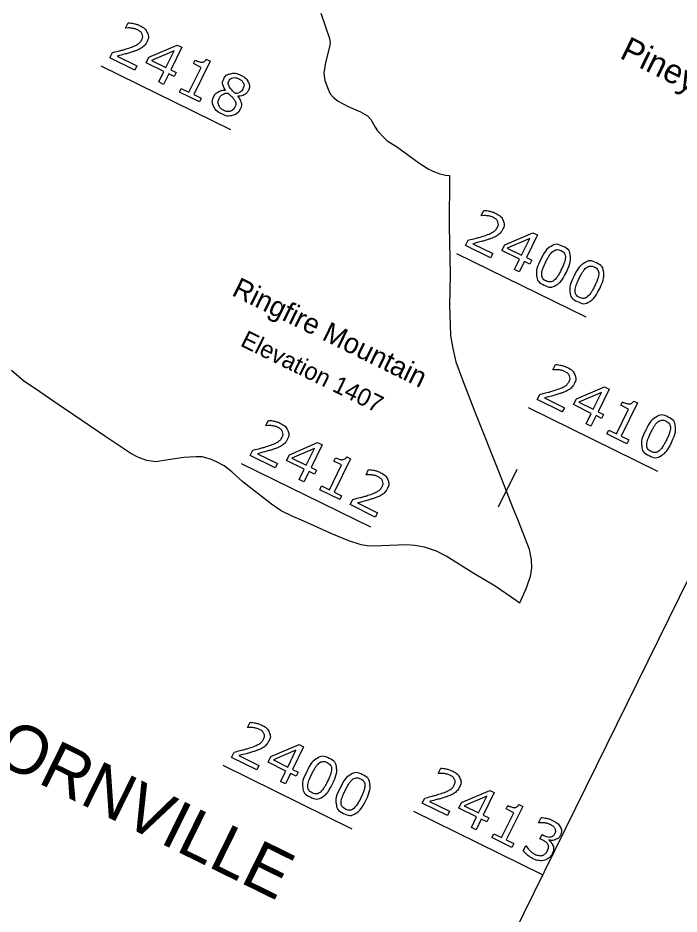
# Model space of a CAD drawing. Extents: x 1428128 to 1430390, y 857947 to 859822.
# Drawn here: x 1428559.3 to 1428679.5, y 859456.4 to 859619.3 of the extents above; entities that cross this region are included whole.
import ezdxf

# ---------------------------------------------------------------- set-up
doc = ezdxf.new("R2010")
doc.units = 0
doc.layers.add('Old_Level_1', color=7, linetype='Continuous')
doc.layers.add('Sheet Title CELL', color=7, linetype='Continuous')

msp = doc.modelspace()

# ---------------------------------------------------------------- linework, layer by layer
at = {"layer": 'Old_Level_1'}
for p, q in [((1428574.42, 859610.64), (1428597.94, 859599.07)), ((1428639.07, 859576.54), (1428662.53, 859564.99)), ((1428652.1, 859548.51), (1428675.56, 859536.97)), ((1428599.93, 859538.37), (1428623.4, 859526.82)), ((1428649.99, 859537.24), (1428646.62, 859530.4)), ((1428596.56, 859483.48), (1428620.03, 859471.94)), ((1428631.22, 859475.14), (1428654.6, 859463.64))]:
    msp.add_line(p, q, dxfattribs=at)
for points in [[(1428578.94, 859617.48), (1428578.9, 859617.51), (1428579.36, 859618.45)], [(1428587.73, 859608.67), (1428586.73, 859609.17), (1428585.8, 859607.27), (1428584.93, 859607.7), (1428585.87, 859609.59), (1428582.64, 859611.18), (1428583.15, 859612.22), (1428588.28, 859614.41), (1428589.11, 859614), (1428587.09, 859609.89), (1428588.09, 859609.4), (1428587.73, 859608.67)], [(1428586.22, 859610.32), (1428587.72, 859613.36), (1428583.61, 859611.6), (1428586.22, 859610.32)], [(1428580.58, 859609.84), (1428576.02, 859612.08), (1428576.49, 859613.03)], [(1428577.35, 859612.4), (1428580.97, 859610.62), (1428580.58, 859609.84)], [(1428592.33, 859604.06), (1428588.68, 859605.85), (1428589.02, 859606.54), (1428590.42, 859605.85), (1428592.64, 859610.36), (1428591.24, 859611.05), (1428591.54, 859611.67)], [(1428593.57, 859611.83), (1428594.27, 859611.49), (1428591.29, 859605.42), (1428592.66, 859604.75), (1428592.33, 859604.06)], [(1428597.05, 859606.2), (1428597.06, 859606.23)], [(1428599.28, 859605.09), (1428599.27, 859605.06)], [(1428643.6, 859583.37), (1428643.55, 859583.4), (1428644.02, 859584.35)], [(1428645.24, 859575.73), (1428640.68, 859577.97), (1428641.15, 859578.93)], [(1428652.39, 859574.57), (1428651.39, 859575.06), (1428650.45, 859573.16), (1428649.59, 859573.59), (1428650.52, 859575.49), (1428647.29, 859577.07), (1428647.81, 859578.11), (1428652.93, 859580.3), (1428653.77, 859579.89), (1428651.74, 859575.78), (1428652.74, 859575.29), (1428652.39, 859574.57)], [(1428650.88, 859576.21), (1428652.37, 859579.25), (1428648.27, 859577.5), (1428650.88, 859576.21)], [(1428642, 859578.29), (1428645.62, 859576.51), (1428645.24, 859575.73)], [(1428656.63, 859555.35), (1428656.58, 859555.38), (1428657.05, 859556.32)], [(1428665.42, 859546.54), (1428664.42, 859547.04), (1428663.49, 859545.14), (1428662.62, 859545.57), (1428663.55, 859547.46), (1428660.33, 859549.05), (1428660.84, 859550.09), (1428665.97, 859552.28), (1428666.8, 859551.87), (1428664.78, 859547.76), (1428665.78, 859547.27), (1428665.42, 859546.54)], [(1428663.91, 859548.19), (1428665.4, 859551.23), (1428661.3, 859549.47), (1428663.91, 859548.19)], [(1428658.27, 859547.71), (1428653.71, 859549.95), (1428654.18, 859550.9)], [(1428655.03, 859550.27), (1428658.65, 859548.49), (1428658.27, 859547.71)], [(1428671.26, 859549.7), (1428671.96, 859549.36), (1428668.98, 859543.29), (1428670.35, 859542.62), (1428670.01, 859541.93)], [(1428670.01, 859541.93), (1428666.37, 859543.72), (1428666.71, 859544.41), (1428668.11, 859543.72), (1428670.33, 859548.23), (1428668.93, 859548.92), (1428669.23, 859549.53)], [(1428604.45, 859545.21), (1428604.41, 859545.23), (1428604.87, 859546.18)], [(1428613.24, 859536.4), (1428612.24, 859536.89), (1428611.31, 859534.99), (1428610.44, 859535.42), (1428611.38, 859537.32), (1428608.15, 859538.9), (1428608.66, 859539.94), (1428613.79, 859542.13), (1428614.62, 859541.72), (1428612.6, 859537.62), (1428613.6, 859537.12), (1428613.24, 859536.4)], [(1428606.09, 859537.56), (1428601.53, 859539.81), (1428602, 859540.76)], [(1428602.85, 859540.12), (1428606.48, 859538.34), (1428606.09, 859537.56)], [(1428611.73, 859538.04), (1428613.23, 859541.08), (1428609.12, 859539.33), (1428611.73, 859538.04)], [(1428617.84, 859531.78), (1428614.19, 859533.58), (1428614.53, 859534.26), (1428615.93, 859533.57), (1428618.15, 859538.08), (1428616.75, 859538.77), (1428617.05, 859539.39)], [(1428619.08, 859539.56), (1428619.78, 859539.21), (1428616.8, 859533.15), (1428618.17, 859532.47), (1428617.84, 859531.78)], [(1428622.64, 859536.26), (1428622.6, 859536.28), (1428623.06, 859537.23)], [(1428624.28, 859528.61), (1428619.72, 859530.86), (1428620.19, 859531.81)], [(1428621.04, 859531.17), (1428624.67, 859529.39), (1428624.28, 859528.61)], [(1428601.09, 859490.32), (1428601.05, 859490.34), (1428601.51, 859491.29)], [(1428609.88, 859481.51), (1428608.88, 859482.01), (1428607.95, 859480.11), (1428607.08, 859480.54), (1428608.01, 859482.43), (1428604.79, 859484.02), (1428605.3, 859485.06), (1428610.43, 859487.25), (1428611.26, 859486.84), (1428609.24, 859482.73), (1428610.24, 859482.24), (1428609.88, 859481.51)], [(1428608.37, 859483.16), (1428609.87, 859486.2), (1428605.76, 859484.44), (1428608.37, 859483.16)], [(1428602.73, 859482.68), (1428598.17, 859484.92), (1428598.64, 859485.87)], [(1428599.49, 859485.24), (1428603.12, 859483.46), (1428602.73, 859482.68)], [(1428635.75, 859481.98), (1428635.71, 859482), (1428636.17, 859482.95)], [(1428644.54, 859473.17), (1428643.54, 859473.66), (1428642.61, 859471.77), (1428641.74, 859472.19), (1428642.67, 859474.09), (1428639.45, 859475.68), (1428639.96, 859476.72), (1428645.09, 859478.91), (1428645.92, 859478.5), (1428643.9, 859474.39), (1428644.9, 859473.9), (1428644.54, 859473.17)], [(1428637.39, 859474.33), (1428632.83, 859476.58), (1428633.3, 859477.53)], [(1428634.15, 859476.9), (1428637.78, 859475.11), (1428637.39, 859474.33)], [(1428643.03, 859474.82), (1428644.53, 859477.85), (1428640.42, 859476.1), (1428643.03, 859474.82)], [(1428650.38, 859476.33), (1428651.08, 859475.98), (1428648.1, 859469.92), (1428649.47, 859469.24), (1428649.13, 859468.56)], [(1428649.13, 859468.56), (1428645.49, 859470.35), (1428645.83, 859471.04), (1428647.23, 859470.35), (1428649.45, 859474.86), (1428648.05, 859475.55), (1428648.35, 859476.16)], [(1428654, 859473), (1428653.95, 859473.02), (1428654.41, 859473.97)], [(1428654.63, 859469.93), (1428654.22, 859470.13), (1428654.59, 859470.88), (1428654.9, 859470.72)], [(1428655.86, 859469.9), (1428655.82, 859469.84)], [(1428651.19, 859467.9), (1428651.65, 859468.84), (1428651.72, 859468.81)]]:
    msp.add_lwpolyline(points, dxfattribs=at)
for points in [[(1428579.36, 859618.45), (1428579.76, 859618.45), (1428580.36, 859618.32), (1428580.97, 859618.19), (1428581.47, 859617.94), (1428582.5, 859617.43), (1428582.85, 859616.64), (1428583.19, 859615.85), (1428582.77, 859615), (1428582.58, 859614.62), (1428582.32, 859614.33), (1428582.06, 859614.05), (1428581.72, 859613.84), (1428581.41, 859613.65), (1428581.04, 859613.5), (1428580.67, 859613.34), (1428580.17, 859613.18), (1428579.45, 859612.94), (1428578.71, 859612.75), (1428577.98, 859612.56), (1428577.35, 859612.4)], [(1428576.49, 859613.03), (1428577.17, 859613.21), (1428577.85, 859613.38), (1428578.52, 859613.55), (1428579.13, 859613.75), (1428580.42, 859614.16), (1428580.98, 859614.5), (1428581.55, 859614.83), (1428581.83, 859615.41), (1428582.09, 859615.93), (1428581.89, 859616.4), (1428581.69, 859616.86), (1428581.06, 859617.17), (1428580.65, 859617.37), (1428580.1, 859617.46), (1428579.55, 859617.56), (1428578.94, 859617.48)], [(1428591.54, 859611.67), (1428591.83, 859611.53), (1428592.18, 859611.41), (1428592.53, 859611.3), (1428592.74, 859611.31), (1428593, 859611.32), (1428593.21, 859611.43), (1428593.41, 859611.55), (1428593.57, 859611.83)], [(1428597.06, 859606.23), (1428596.66, 859606.78), (1428596.57, 859607.25), (1428596.48, 859607.73), (1428596.73, 859608.24), (1428597.11, 859609), (1428597.98, 859609.2), (1428598.85, 859609.4), (1428599.82, 859608.92), (1428600.83, 859608.43), (1428601.19, 859607.65), (1428601.55, 859606.87), (1428601.19, 859606.12), (1428600.96, 859605.67), (1428600.46, 859605.37), (1428599.96, 859605.07), (1428599.28, 859605.09)], [(1428600.29, 859606.55), (1428600.53, 859607.04), (1428600.3, 859607.51), (1428600.06, 859607.98), (1428599.48, 859608.26), (1428598.91, 859608.54), (1428598.42, 859608.45), (1428597.92, 859608.36), (1428597.69, 859607.9), (1428597.53, 859607.57), (1428597.6, 859607.25), (1428597.66, 859606.92), (1428597.94, 859606.55), (1428598.07, 859606.39), (1428598.32, 859606.1), (1428598.57, 859605.82), (1428598.83, 859605.58), (1428599.42, 859605.66), (1428599.75, 859605.9), (1428600.08, 859606.13), (1428600.29, 859606.55)], [(1428599.75, 859602.74), (1428599.32, 859601.87), (1428598.35, 859601.62), (1428597.39, 859601.38), (1428596.35, 859601.89), (1428595.26, 859602.43), (1428594.89, 859603.31), (1428594.52, 859604.19), (1428594.95, 859605.08), (1428595.23, 859605.64), (1428595.78, 859605.93), (1428596.33, 859606.22), (1428597.05, 859606.2)], [(1428598.78, 859603.11), (1428598.98, 859603.53), (1428598.92, 859603.87), (1428598.86, 859604.21), (1428598.45, 859604.72), (1428598.29, 859604.93), (1428598.08, 859605.14), (1428597.86, 859605.35), (1428597.52, 859605.71), (1428597, 859605.69), (1428596.57, 859605.43), (1428596.14, 859605.17), (1428595.9, 859604.69), (1428595.6, 859604.08), (1428595.83, 859603.48), (1428596.05, 859602.88), (1428596.7, 859602.56), (1428597.36, 859602.23), (1428597.92, 859602.38), (1428598.48, 859602.52), (1428598.78, 859603.11)], [(1428599.27, 859605.06), (1428599.77, 859604.48), (1428599.91, 859603.92), (1428600.05, 859603.35), (1428599.75, 859602.74)], [(1428644.02, 859584.35), (1428644.42, 859584.35), (1428645.02, 859584.21), (1428645.62, 859584.08), (1428646.12, 859583.83), (1428647.16, 859583.32), (1428647.5, 859582.53), (1428647.84, 859581.75), (1428647.42, 859580.89), (1428647.23, 859580.51), (1428646.97, 859580.22), (1428646.71, 859579.94), (1428646.38, 859579.73), (1428646.06, 859579.54), (1428645.69, 859579.39), (1428645.32, 859579.23), (1428644.82, 859579.07), (1428644.1, 859578.83), (1428643.37, 859578.64), (1428642.63, 859578.45), (1428642, 859578.29)], [(1428641.15, 859578.93), (1428641.82, 859579.1), (1428642.5, 859579.27), (1428643.18, 859579.44), (1428643.79, 859579.64), (1428645.07, 859580.05), (1428645.64, 859580.39), (1428646.2, 859580.73), (1428646.48, 859581.3), (1428646.74, 859581.82), (1428646.54, 859582.29), (1428646.34, 859582.76), (1428645.72, 859583.06), (1428645.31, 859583.26), (1428644.75, 859583.36), (1428644.2, 859583.45), (1428643.6, 859583.37)], [(1428659.01, 859573.14), (1428658.12, 859571.32), (1428657.13, 859570.75), (1428656.15, 859570.18), (1428654.96, 859570.77), (1428653.75, 859571.37), (1428653.61, 859572.5), (1428653.48, 859573.64), (1428654.35, 859575.42), (1428655.24, 859577.22), (1428656.22, 859577.8), (1428657.21, 859578.38), (1428658.41, 859577.79), (1428659.62, 859577.19), (1428659.75, 859576.04), (1428659.88, 859574.9), (1428659.01, 859573.14)], [(1428656.81, 859571.67), (1428657.15, 859571.96), (1428657.45, 859572.43), (1428657.75, 859572.89), (1428658.09, 859573.59), (1428658.43, 859574.28), (1428658.62, 859574.81), (1428658.82, 859575.35), (1428658.83, 859575.78), (1428658.84, 859576.21), (1428658.66, 859576.52), (1428658.47, 859576.83), (1428658.04, 859577.04), (1428657.62, 859577.25), (1428657.25, 859577.21), (1428656.89, 859577.17), (1428656.55, 859576.89), (1428656.23, 859576.63), (1428655.91, 859576.12), (1428655.59, 859575.61), (1428655.27, 859574.97), (1428654.92, 859574.26), (1428654.74, 859573.76), (1428654.55, 859573.26), (1428654.53, 859572.81), (1428654.51, 859572.38), (1428654.69, 859572.06), (1428654.87, 859571.74), (1428655.32, 859571.52), (1428655.75, 859571.31), (1428656.11, 859571.35), (1428656.48, 859571.39), (1428656.81, 859571.67)], [(1428665.07, 859570.16), (1428664.18, 859568.34), (1428663.2, 859567.77), (1428662.21, 859567.2), (1428661.02, 859567.79), (1428659.81, 859568.38), (1428659.67, 859569.52), (1428659.54, 859570.65), (1428660.42, 859572.44), (1428661.3, 859574.23), (1428662.29, 859574.81), (1428663.27, 859575.39), (1428664.47, 859574.8), (1428665.68, 859574.21), (1428665.81, 859573.06), (1428665.94, 859571.92), (1428665.07, 859570.16)], [(1428662.87, 859568.69), (1428663.21, 859568.97), (1428663.51, 859569.44), (1428663.81, 859569.91), (1428664.16, 859570.61), (1428664.49, 859571.29), (1428664.69, 859571.83), (1428664.88, 859572.36), (1428664.89, 859572.8), (1428664.9, 859573.22), (1428664.72, 859573.53), (1428664.53, 859573.84), (1428664.1, 859574.06), (1428663.68, 859574.26), (1428663.31, 859574.22), (1428662.95, 859574.19), (1428662.61, 859573.91), (1428662.29, 859573.65), (1428661.97, 859573.14), (1428661.65, 859572.63), (1428661.33, 859571.98), (1428660.99, 859571.28), (1428660.8, 859570.78), (1428660.62, 859570.28), (1428660.6, 859569.82), (1428660.57, 859569.4), (1428660.75, 859569.08), (1428660.93, 859568.76), (1428661.39, 859568.53), (1428661.81, 859568.33), (1428662.18, 859568.36), (1428662.54, 859568.4), (1428662.87, 859568.69)], [(1428657.05, 859556.32), (1428657.45, 859556.32), (1428658.05, 859556.19), (1428658.65, 859556.06), (1428659.15, 859555.81), (1428660.19, 859555.3), (1428660.53, 859554.51), (1428660.87, 859553.72), (1428660.45, 859552.87), (1428660.27, 859552.49), (1428660, 859552.2), (1428659.74, 859551.92), (1428659.41, 859551.71), (1428659.09, 859551.52), (1428658.72, 859551.37), (1428658.35, 859551.21), (1428657.85, 859551.05), (1428657.13, 859550.81), (1428656.4, 859550.62), (1428655.66, 859550.43), (1428655.03, 859550.27)], [(1428654.18, 859550.9), (1428654.85, 859551.08), (1428655.53, 859551.25), (1428656.21, 859551.42), (1428656.82, 859551.62), (1428658.1, 859552.03), (1428658.67, 859552.37), (1428659.23, 859552.7), (1428659.52, 859553.28), (1428659.77, 859553.8), (1428659.57, 859554.27), (1428659.37, 859554.73), (1428658.75, 859555.04), (1428658.34, 859555.24), (1428657.79, 859555.33), (1428657.23, 859555.43), (1428656.63, 859555.35)], [(1428669.23, 859549.53), (1428669.51, 859549.39), (1428669.86, 859549.28), (1428670.21, 859549.17), (1428670.42, 859549.18), (1428670.69, 859549.19), (1428670.89, 859549.3), (1428671.1, 859549.42), (1428671.26, 859549.7)], [(1428678.11, 859542.13), (1428677.21, 859540.32), (1428676.23, 859539.75), (1428675.24, 859539.18), (1428674.05, 859539.77), (1428672.84, 859540.36), (1428672.7, 859541.5), (1428672.57, 859542.63), (1428673.45, 859544.41), (1428674.33, 859546.21), (1428675.32, 859546.79), (1428676.31, 859547.37), (1428677.5, 859546.78), (1428678.71, 859546.18), (1428678.84, 859545.04), (1428678.97, 859543.89), (1428678.11, 859542.13)], [(1428602, 859540.76), (1428602.68, 859540.93), (1428603.36, 859541.1), (1428604.03, 859541.27), (1428604.64, 859541.47), (1428605.93, 859541.88), (1428606.49, 859542.22), (1428607.06, 859542.56), (1428607.34, 859543.13), (1428607.6, 859543.65), (1428607.4, 859544.12), (1428607.19, 859544.59), (1428606.57, 859544.89), (1428606.16, 859545.1), (1428605.61, 859545.19), (1428605.06, 859545.28), (1428604.45, 859545.21)], [(1428604.87, 859546.18), (1428605.27, 859546.18), (1428605.87, 859546.04), (1428606.47, 859545.91), (1428606.98, 859545.66), (1428608.01, 859545.15), (1428608.36, 859544.36), (1428608.7, 859543.58), (1428608.28, 859542.72), (1428608.09, 859542.34), (1428607.83, 859542.05), (1428607.57, 859541.77), (1428607.23, 859541.57), (1428606.92, 859541.37), (1428606.55, 859541.22), (1428606.18, 859541.06), (1428605.67, 859540.9), (1428604.96, 859540.67), (1428604.22, 859540.47), (1428603.49, 859540.28), (1428602.85, 859540.12)], [(1428675.91, 859540.66), (1428676.24, 859540.95), (1428676.54, 859541.42), (1428676.84, 859541.89), (1428677.19, 859542.58), (1428677.53, 859543.27), (1428677.72, 859543.81), (1428677.91, 859544.34), (1428677.92, 859544.77), (1428677.94, 859545.2), (1428677.75, 859545.51), (1428677.56, 859545.82), (1428677.13, 859546.03), (1428676.71, 859546.24), (1428676.35, 859546.2), (1428675.98, 859546.16), (1428675.64, 859545.89), (1428675.32, 859545.63), (1428675, 859545.12), (1428674.68, 859544.6), (1428674.37, 859543.96), (1428674.02, 859543.26), (1428673.83, 859542.76), (1428673.65, 859542.26), (1428673.63, 859541.8), (1428673.6, 859541.37), (1428673.78, 859541.05), (1428673.97, 859540.73), (1428674.42, 859540.51), (1428674.84, 859540.3), (1428675.21, 859540.34), (1428675.58, 859540.38), (1428675.91, 859540.66)], [(1428617.05, 859539.39), (1428617.34, 859539.25), (1428617.69, 859539.14), (1428618.03, 859539.02), (1428618.25, 859539.03), (1428618.51, 859539.04), (1428618.72, 859539.16), (1428618.92, 859539.27), (1428619.08, 859539.56)], [(1428623.06, 859537.23), (1428623.46, 859537.23), (1428624.06, 859537.09), (1428624.66, 859536.96), (1428625.17, 859536.71), (1428626.2, 859536.2), (1428626.54, 859535.42), (1428626.89, 859534.63), (1428626.47, 859533.77), (1428626.28, 859533.39), (1428626.02, 859533.11), (1428625.76, 859532.82), (1428625.42, 859532.62), (1428625.11, 859532.42), (1428624.74, 859532.27), (1428624.37, 859532.11), (1428623.86, 859531.95), (1428623.15, 859531.72), (1428622.41, 859531.52), (1428621.68, 859531.33), (1428621.04, 859531.17)], [(1428620.19, 859531.81), (1428620.87, 859531.98), (1428621.54, 859532.15), (1428622.22, 859532.32), (1428622.83, 859532.52), (1428624.12, 859532.93), (1428624.68, 859533.27), (1428625.25, 859533.61), (1428625.53, 859534.18), (1428625.79, 859534.7), (1428625.58, 859535.17), (1428625.38, 859535.64), (1428624.76, 859535.94), (1428624.35, 859536.15), (1428623.8, 859536.24), (1428623.25, 859536.33), (1428622.64, 859536.26)], [(1428601.51, 859491.29), (1428601.91, 859491.29), (1428602.51, 859491.16), (1428603.11, 859491.03), (1428603.61, 859490.78), (1428604.65, 859490.27), (1428604.99, 859489.48), (1428605.34, 859488.69), (1428604.92, 859487.84), (1428604.73, 859487.46), (1428604.47, 859487.17), (1428604.21, 859486.89), (1428603.87, 859486.68), (1428603.56, 859486.49), (1428603.19, 859486.34), (1428602.81, 859486.18), (1428602.31, 859486.02), (1428601.6, 859485.78), (1428600.86, 859485.59), (1428600.13, 859485.4), (1428599.49, 859485.24)], [(1428598.64, 859485.87), (1428599.32, 859486.05), (1428599.99, 859486.22), (1428600.67, 859486.39), (1428601.28, 859486.59), (1428602.57, 859487), (1428603.13, 859487.34), (1428603.7, 859487.67), (1428603.98, 859488.25), (1428604.24, 859488.77), (1428604.03, 859489.24), (1428603.83, 859489.7), (1428603.21, 859490.01), (1428602.8, 859490.21), (1428602.25, 859490.3), (1428601.7, 859490.4), (1428601.09, 859490.32)], [(1428616.5, 859480.09), (1428615.61, 859478.27), (1428614.63, 859477.7), (1428613.64, 859477.13), (1428612.45, 859477.72), (1428611.24, 859478.31), (1428611.1, 859479.45), (1428610.97, 859480.58), (1428611.85, 859482.37), (1428612.73, 859484.16), (1428613.72, 859484.74), (1428614.7, 859485.32), (1428615.9, 859484.73), (1428617.11, 859484.14), (1428617.24, 859482.99), (1428617.37, 859481.85), (1428616.5, 859480.09)], [(1428614.31, 859478.62), (1428614.64, 859478.91), (1428614.94, 859479.37), (1428615.24, 859479.84), (1428615.59, 859480.54), (1428615.93, 859481.23), (1428616.12, 859481.76), (1428616.31, 859482.29), (1428616.32, 859482.73), (1428616.34, 859483.15), (1428616.15, 859483.46), (1428615.96, 859483.78), (1428615.53, 859483.99), (1428615.11, 859484.2), (1428614.75, 859484.16), (1428614.38, 859484.12), (1428614.04, 859483.84), (1428613.72, 859483.58), (1428613.4, 859483.07), (1428613.08, 859482.56), (1428612.76, 859481.91), (1428612.42, 859481.21), (1428612.23, 859480.71), (1428612.05, 859480.21), (1428612.03, 859479.75), (1428612, 859479.33), (1428612.18, 859479.01), (1428612.37, 859478.69), (1428612.82, 859478.47), (1428613.24, 859478.26), (1428613.61, 859478.3), (1428613.98, 859478.33), (1428614.31, 859478.62)], [(1428636.17, 859482.95), (1428636.57, 859482.95), (1428637.17, 859482.82), (1428637.77, 859482.68), (1428638.28, 859482.44), (1428639.31, 859481.93), (1428639.65, 859481.14), (1428640, 859480.35), (1428639.58, 859479.5), (1428639.39, 859479.11), (1428639.13, 859478.83), (1428638.87, 859478.54), (1428638.53, 859478.34), (1428638.22, 859478.15), (1428637.85, 859477.99), (1428637.48, 859477.84), (1428636.97, 859477.68), (1428636.26, 859477.44), (1428635.52, 859477.25), (1428634.79, 859477.06), (1428634.15, 859476.9)], [(1428622.57, 859477.1), (1428621.67, 859475.29), (1428620.69, 859474.72), (1428619.71, 859474.15), (1428618.51, 859474.74), (1428617.3, 859475.33), (1428617.17, 859476.47), (1428617.03, 859477.6), (1428617.91, 859479.38), (1428618.79, 859481.18), (1428619.78, 859481.76), (1428620.77, 859482.34), (1428621.96, 859481.75), (1428623.18, 859481.15), (1428623.3, 859480.01), (1428623.43, 859478.86), (1428622.57, 859477.1)], [(1428620.37, 859475.63), (1428620.71, 859475.92), (1428621.01, 859476.39), (1428621.31, 859476.86), (1428621.65, 859477.55), (1428621.99, 859478.24), (1428622.18, 859478.78), (1428622.37, 859479.31), (1428622.39, 859479.74), (1428622.4, 859480.17), (1428622.21, 859480.48), (1428622.03, 859480.79), (1428621.6, 859481), (1428621.17, 859481.21), (1428620.81, 859481.17), (1428620.44, 859481.13), (1428620.1, 859480.86), (1428619.79, 859480.6), (1428619.47, 859480.09), (1428619.14, 859479.57), (1428618.83, 859478.93), (1428618.48, 859478.23), (1428618.3, 859477.73), (1428618.11, 859477.23), (1428618.09, 859476.77), (1428618.06, 859476.34), (1428618.25, 859476.02), (1428618.43, 859475.7), (1428618.88, 859475.48), (1428619.31, 859475.27), (1428619.67, 859475.31), (1428620.04, 859475.35), (1428620.37, 859475.63)], [(1428633.3, 859477.53), (1428633.98, 859477.7), (1428634.65, 859477.87), (1428635.33, 859478.05), (1428635.94, 859478.24), (1428637.23, 859478.66), (1428637.79, 859478.99), (1428638.36, 859479.33), (1428638.64, 859479.9), (1428638.9, 859480.43), (1428638.69, 859480.89), (1428638.49, 859481.36), (1428637.87, 859481.67), (1428637.46, 859481.87), (1428636.91, 859481.96), (1428636.36, 859482.05), (1428635.75, 859481.98)], [(1428648.35, 859476.16), (1428648.64, 859476.02), (1428648.99, 859475.91), (1428649.33, 859475.8), (1428649.55, 859475.8), (1428649.81, 859475.81), (1428650.01, 859475.93), (1428650.22, 859476.04), (1428650.38, 859476.33)], [(1428654.9, 859470.72), (1428655.59, 859470.38), (1428656.14, 859470.47), (1428656.69, 859470.55), (1428656.96, 859471.11), (1428657.08, 859471.35), (1428657.07, 859471.59), (1428657.06, 859471.82), (1428656.93, 859472.03), (1428656.79, 859472.24), (1428656.59, 859472.4), (1428656.39, 859472.55), (1428656.11, 859472.69), (1428655.68, 859472.9), (1428655.12, 859472.99), (1428654.56, 859473.07), (1428654, 859473)], [(1428654.41, 859473.97), (1428654.81, 859473.97), (1428655.41, 859473.84), (1428656.02, 859473.71), (1428656.52, 859473.46), (1428657.01, 859473.22), (1428657.34, 859472.94), (1428657.67, 859472.67), (1428657.88, 859472.32), (1428658.1, 859471.94), (1428658.11, 859471.55), (1428658.13, 859471.16), (1428657.93, 859470.75), (1428657.65, 859470.19), (1428657.05, 859469.97), (1428656.45, 859469.74), (1428655.86, 859469.9)], [(1428651.72, 859468.81), (1428651.98, 859468.36), (1428652.42, 859467.94), (1428652.86, 859467.52), (1428653.34, 859467.28), (1428653.63, 859467.14), (1428653.99, 859467.08), (1428654.36, 859467.01), (1428654.65, 859467.1), (1428654.96, 859467.2), (1428655.18, 859467.39), (1428655.4, 859467.58), (1428655.58, 859467.95), (1428655.76, 859468.31), (1428655.76, 859468.6), (1428655.76, 859468.9), (1428655.62, 859469.13), (1428655.49, 859469.37), (1428655.22, 859469.57), (1428654.96, 859469.76), (1428654.63, 859469.93)], [(1428655.82, 859469.84), (1428656.02, 859469.69), (1428656.25, 859469.44), (1428656.47, 859469.19), (1428656.58, 859468.92)], [(1428656.58, 859468.92), (1428656.7, 859468.62), (1428656.7, 859468.26), (1428656.69, 859467.89), (1428656.46, 859467.43), (1428656.24, 859466.96), (1428655.88, 859466.66), (1428655.52, 859466.36), (1428655.08, 859466.22), (1428654.59, 859466.07), (1428654.05, 859466.15), (1428653.52, 859466.22), (1428652.97, 859466.49), (1428652.41, 859466.77), (1428651.93, 859467.17), (1428651.46, 859467.57), (1428651.19, 859467.9)]]:
    msp.add_open_spline(points, degree=3, dxfattribs=at)
at = {"layer": 'Sheet Title CELL'}
msp.add_line((1428763.48, 859684.67), (1428622.2, 859397.54), dxfattribs=at)
for points in [[(1428614.37, 859620.23), (1428615.93, 859615.62), (1428616.07, 859614.77), (1428615.9, 859613.85), (1428615.23, 859611.21), (1428614.92, 859609.28), (1428615.14, 859607.95), (1428615.71, 859606.42), (1428616.09, 859605.55), (1428616.66, 859604.86), (1428617.55, 859604.2), (1428619.38, 859603.27), (1428621.6, 859602.27), (1428622.84, 859601.54), (1428623.46, 859600.89), (1428624.24, 859599.51), (1428624.68, 859598.82), (1428625.97, 859597.5), (1428626.47, 859597), (1428628.11, 859595.94), (1428630.38, 859594.33), (1428632.21, 859592.99), (1428633.9, 859591.91), (1428634.75, 859591.49), (1428635.99, 859591.01), (1428637.02, 859590.75), (1428637.77, 859590.67)], [(1428637.77, 859590.67), (1428637.73, 859581.49), (1428637.87, 859572.65), (1428637.77, 859567.12), (1428637.98, 859561.63), (1428638.35, 859559.27), (1428638.94, 859556.8), (1428640.11, 859553.57), (1428642.39, 859547.71), (1428646.8, 859536.67), (1428649.21, 859530.38), (1428650.25, 859527.9), (1428652.25, 859522.74), (1428652.61, 859520.82), (1428652.66, 859519.37), (1428652.45, 859517.82), (1428651.69, 859515.69), (1428650.49, 859512.96)], [(1428567.64, 859548.42), (1428563.3, 859551.37), (1428560.37, 859553.37), (1428558.15, 859555.23)], [(1428650.49, 859512.96), (1428649.94, 859513.36), (1428646.05, 859516.01), (1428642.2, 859518.37), (1428637.16, 859521.49), (1428635.38, 859522.39), (1428633.25, 859523.16), (1428631.46, 859523.45), (1428629.94, 859523.58), (1428625.39, 859523.35), (1428623.19, 859523.34), (1428621.69, 859523.56), (1428619.47, 859524.3), (1428616.39, 859525.56), (1428611.27, 859527.88), (1428609.32, 859528.7), (1428607.19, 859529.76), (1428605.44, 859530.92), (1428600.26, 859534.97), (1428598.2, 859536.8), (1428596.82, 859537.89), (1428595.32, 859538.73), (1428594.33, 859539.12), (1428592.82, 859539.53), (1428591.68, 859539.58), (1428589.47, 859539.45), (1428586.66, 859539.02), (1428584.39, 859538.67), (1428582.73, 859538.88), (1428581.24, 859539.43), (1428579.84, 859540.17), (1428575.32, 859543.19), (1428567.91, 859548.24), (1428567.64, 859548.42)]]:
    msp.add_lwpolyline(points, dxfattribs=at)

# ---------------------------------------------------------------- texts
at = {"layer": 'Old_Level_1'}
for s, height, p in [('Piney Mountain', 4.4, (1428668.51, 859612.14)), ('Ringfire Mountain', 3.6667, (1428598.02, 859569)), ('Elevation 1407', 3.1667, (1428599.58, 859559.81)), ('OSBORNVILLE', 8.75, (1428532.38, 859495.29))]:
    msp.add_text(s, height=height, rotation=333.8001, dxfattribs=at).set_placement(p)

doc.saveas('drawing.dxf')
